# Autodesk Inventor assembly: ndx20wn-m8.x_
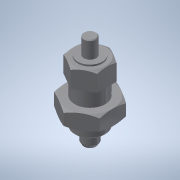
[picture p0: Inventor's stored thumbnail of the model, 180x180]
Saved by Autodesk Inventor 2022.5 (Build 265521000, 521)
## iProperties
Part Number: ndx20wn-m8.x_
Material: 一般
Document SubType Name: Assembly
Designer: ImaoCorp
Sending System: SOLIDWORKS 2017-2017317
MC: AMD64
MC_MODEL: Intel64 Family 6 Model 60 Stepping 3, GenuineIntel
OS: Windows_NT
FRU: Parasolid Version 29.0, build 201,  4-17-2017
FORMAT: text
GUISE: transmit
KEY: ndx20wn-m8
FILE: ndx20wn-m8.x_t
DATE: Wed Sep 04 15:30:33 2019
Author: ImaoCorp
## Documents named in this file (3)
- X:\14_SW2022-Inv2022\00_全2023-1023新製品(TCC)まで\n\ndx20wn-m8\NDX20WN-M8.iam
- X:\14_SW2022-Inv2022\00_全2023-1023新製品(TCC)まで\n\ndx20wn-m8\ndx20wn-m8_01.ipt
- X:\14_SW2022-Inv2022\00_全2023-1023新製品(TCC)まで\n\ndx20wn-m8\ndx20wn-m8_02.ipt
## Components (2 placed, 2 different names)
1. ndx20wn-m8_01
2. ndx20wn-m8_02
